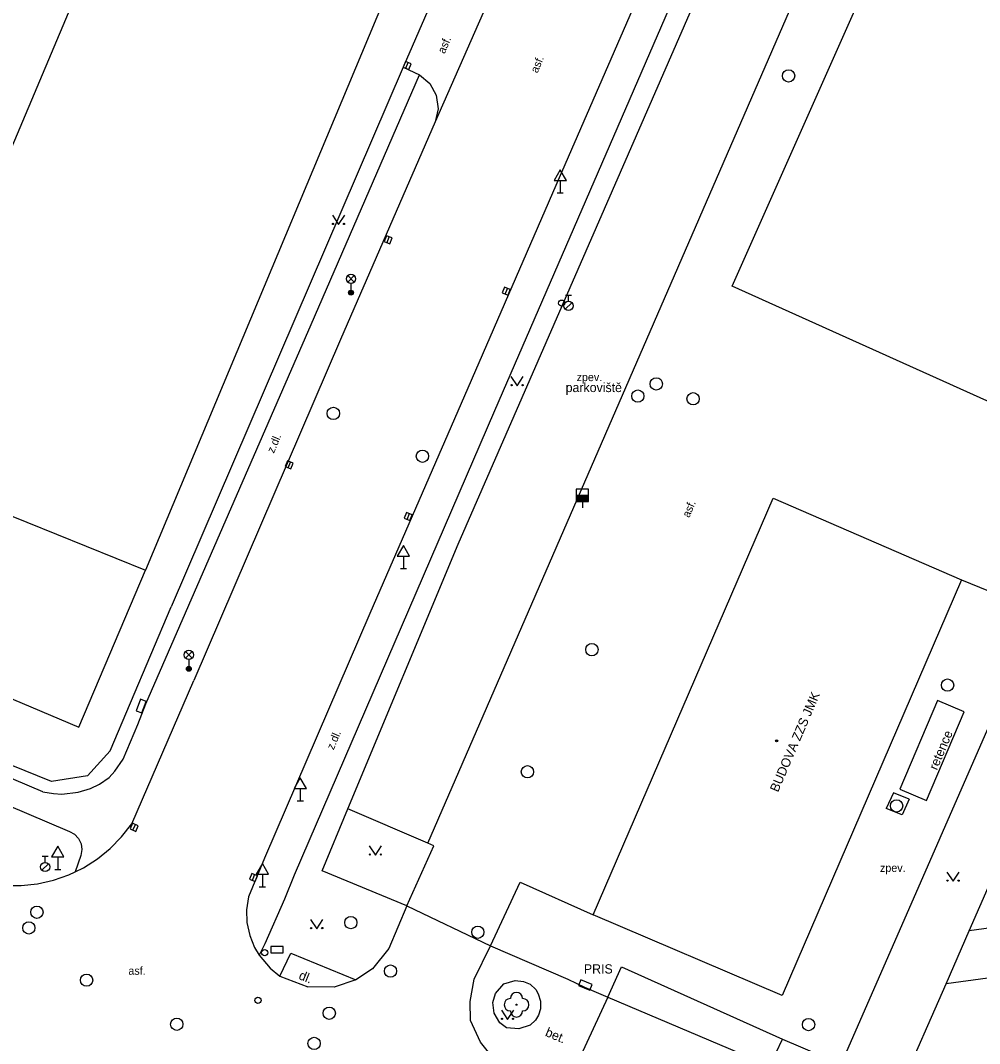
# Model space of a CAD drawing. Extents: x -596024 to -594475, y -1163820 to -1161957.
# Drawn here: x -594753.9 to -594676, y -1162375 to -1162292 of the extents above; entities that cross this region are included whole.
import ezdxf

# ---------------------------------------------------------------- set-up
doc = ezdxf.new("R2010")
doc.units = 0
for name, color, linetype in [('Level 10', 7, 'Continuous'), ('Level 11', 7, 'Continuous'), ('Level 22', 7, 'Continuous'), ('Level 24', 7, 'Continuous'), ('Level 27', 7, 'Continuous'), ('Level 28', 7, 'Continuous'), ('Level 33', 7, 'Continuous'), ('Level 34', 7, 'Continuous'), ('Level 36', 7, 'Continuous'), ('Level 39', 7, 'Continuous'), ('Level 40', 7, 'Continuous'), ('Level 41', 7, 'Continuous'), ('Level 42', 7, 'Continuous'), ('Level 43', 7, 'Continuous'), ('Level 5', 7, 'Continuous'), ('Level 7', 7, 'Continuous'), ('Level 8', 7, 'Continuous')]:
    doc.layers.add(name, color=color, linetype=linetype)

msp = doc.modelspace()

# ---------------------------------------------------------------- linework, layer by layer
at = {"layer": 'Level 10'}
for points in [[(-594702.69, -1162287.55), (-594710.41, -1162305.36), (-594717.82, -1162322.43), (-594725.53, -1162340.1), (-594734.07, -1162359.95), (-594735.38, -1162363.09)], [(-594714.72, -1162287.68), (-594720.21, -1162300.18)], [(-594720.21, -1162300.18), (-594727.89, -1162317.86), (-594739.81, -1162345.52)], [(-594744.85, -1162357.18), (-594739.81, -1162345.52)], [(-594749.43, -1162361.06), (-594748.76, -1162360.73), (-594747.63, -1162360.01), (-594746.6, -1162359.18), (-594745.67, -1162358.23), (-594744.85, -1162357.18)], [(-594759.02, -1162361.25), (-594757.77, -1162361.71), (-594756.48, -1162362.02), (-594755.16, -1162362.18), (-594753.83, -1162362.18), (-594752.51, -1162362.04), (-594751.21, -1162361.75), (-594749.95, -1162361.31), (-594749.43, -1162361.06)], [(-594735.38, -1162363.09), (-594735.53, -1162364.14), (-594735.49, -1162365.19), (-594735.27, -1162366.23), (-594734.87, -1162367.21), (-594734.51, -1162367.83)], [(-594722.52, -1162363.83), (-594723.98, -1162367.29), (-594725.3, -1162368.93), (-594726.65, -1162369.84)], [(-594722.52, -1162363.83), (-594715.71, -1162367.06)], [(-594715.21, -1162376.53), (-594716.54, -1162374.89), (-594717.34, -1162373.13), (-594717.37, -1162371.6), (-594717.05, -1162369.79), (-594715.71, -1162367.06)], [(-594734.51, -1162367.83), (-594733.61, -1162368.89)], [(-594733.61, -1162368.89), (-594732.83, -1162369.53)], [(-594732.83, -1162369.53), (-594730.54, -1162370.41)], [(-594726.65, -1162369.84), (-594728.42, -1162370.43), (-594730.54, -1162370.41)]]:
    msp.add_lwpolyline(points, dxfattribs=at)
at = {"layer": 'Level 11'}
for points in [[(-594682.2, -1162247.11), (-594684.47, -1162252.23), (-594693.08, -1162272.1), (-594700.25, -1162288.69), (-594715.41, -1162323.63)], [(-594736.89, -1162272.33), (-594719.88, -1162279.55), (-594743.74, -1162336.57)], [(-594718.34, -1162334.47), (-594696.72, -1162284.88), (-594694.07, -1162278.81), (-594689.66, -1162280.67)], [(-594719.88, -1162279.55), (-594716.51, -1162281.14), (-594719.82, -1162288.82), (-594722.8, -1162295.75), (-594741.65, -1162339.55)], [(-594687.26, -1162376.68), (-594671.17, -1162339.92), (-594665.63, -1162327.25), (-594696.11, -1162313.53), (-594685.6, -1162289.88), (-594682.8, -1162283.58)], [(-594720.8, -1162358.74), (-594690.02, -1162287.83), (-594696.72, -1162284.88)], [(-594722.8, -1162295.75), (-594721.48, -1162296.37)], [(-594744.34, -1162349.11), (-594743.71, -1162347.44), (-594730.27, -1162316.63), (-594721.48, -1162296.37)], [(-594721.48, -1162296.37), (-594720.65, -1162297.08), (-594720.12, -1162298.03), (-594719.97, -1162299.12), (-594720.21, -1162300.18)], [(-594715.41, -1162323.63), (-594731.66, -1162361.34)], [(-594765.42, -1162327.81), (-594743.74, -1162336.57)], [(-594752.07, -1162354.57), (-594762.07, -1162350.31), (-594773.85, -1162345.29), (-594804.52, -1162332.02)], [(-594806.31, -1162333.82), (-594774.887, -1162347.169), (-594749.91, -1162357.78)], [(-594677.49, -1162337.37), (-594671.17, -1162339.92)], [(-594745.53, -1162351.93), (-594744.34, -1162349.11)], [(-594752.07, -1162354.57), (-594751.207, -1162354.712), (-594750.51, -1162354.75), (-594749.207, -1162354.585), (-594748.191, -1162354.299), (-594747.461, -1162353.95), (-594746.676, -1162353.412), (-594746.223, -1162352.886), (-594745.53, -1162351.93)], [(-594722.52, -1162363.83), (-594720.33, -1162358.95), (-594720.8, -1162358.74), (-594727.3, -1162355.94)], [(-594749.91, -1162357.78), (-594749.5, -1162358.01), (-594749.17, -1162358.36), (-594748.96, -1162358.79), (-594748.9, -1162359.26), (-594748.97, -1162359.73)], [(-594748.97, -1162359.73), (-594749.43, -1162361.06)], [(-594731.66, -1162361.34), (-594732.45, -1162363.28), (-594734.03, -1162366.9), (-594734.51, -1162367.83)], [(-594715.71, -1162367.06), (-594713.31, -1162361.91), (-594707.38, -1162364.56)], [(-594658.45, -1162363.35), (-594676.86, -1162365.85)], [(-594732.83, -1162369.53), (-594731.92, -1162367.67), (-594726.65, -1162369.84)], [(-594658.03, -1162367.34), (-594678.74, -1162370.15)], [(-594706.2, -1162371.24), (-594705.09, -1162368.77), (-594692.01, -1162374.65)], [(-594715.42, -1162372.53), (-594715.53, -1162371.66), (-594715.32, -1162370.94), (-594714.64, -1162370.16), (-594713.73, -1162369.89), (-594713.03, -1162369.96), (-594712.5, -1162370.19), (-594712.04, -1162370.61)], [(-594712.04, -1162370.61), (-594711.84, -1162370.96)], [(-594711.84, -1162370.96), (-594711.65, -1162371.56)], [(-594706.2, -1162371.24), (-594709.76, -1162378.95)], [(-594711.65, -1162371.56), (-594711.66, -1162372.2), (-594711.83, -1162372.69), (-594712.08, -1162373.12), (-594712.51, -1162373.5), (-594713.41, -1162373.8), (-594714.42, -1162373.72), (-594714.96, -1162373.32), (-594715.42, -1162372.53)]]:
    msp.add_lwpolyline(points, dxfattribs=at)
at = {"layer": 'Level 22'}
msp.add_circle((-594713.61, -1162371.85), 0.05, dxfattribs=at)
for centre, start, end in [((-594714.11, -1162371.85), 90, 270), ((-594713.61, -1162371.35), 0, 180), ((-594713.11, -1162371.85), 270, 90), ((-594713.61, -1162372.35), 180, 0)]:
    msp.add_arc(centre, 0.5, start, end, dxfattribs=at)
at = {"layer": 'Level 24'}
for points in [[(-594744.033, -1162348.167), (-594743.662, -1162347.238), (-594744.127, -1162347.053), (-594744.498, -1162347.982)], [(-594733.55, -1162367.64), (-594732.55, -1162367.64), (-594732.55, -1162367.14), (-594733.55, -1162367.14)], [(-594708.578, -1162370.29), (-594707.653, -1162370.672), (-594707.462, -1162370.21), (-594708.387, -1162369.828)]]:
    msp.add_lwpolyline(points, close=True, dxfattribs=at)
at = {"layer": 'Level 27'}
for p, q in [((-594722.585, -1162295.831), (-594722.395, -1162295.369)), ((-594724.122, -1162309.982), (-594723.938, -1162309.518)), ((-594714.532, -1162314.162), (-594714.348, -1162313.698)), ((-594732.152, -1162328.262), (-594731.968, -1162327.798)), ((-594722.492, -1162332.452), (-594722.308, -1162331.988)), ((-594744.751, -1162357.679), (-594744.549, -1162357.221)), ((-594735.052, -1162361.762), (-594734.868, -1162361.298))]:
    msp.add_line(p, q, dxfattribs=at)
for points in [[(-594722.354, -1162295.926), (-594722.164, -1162295.464), (-594722.626, -1162295.274), (-594722.816, -1162295.736)], [(-594723.89, -1162310.075), (-594723.705, -1162309.61), (-594724.17, -1162309.425), (-594724.355, -1162309.89)], [(-594714.3, -1162314.255), (-594714.115, -1162313.79), (-594714.58, -1162313.605), (-594714.765, -1162314.07)], [(-594731.92, -1162328.355), (-594731.735, -1162327.89), (-594732.2, -1162327.705), (-594732.385, -1162328.17)], [(-594722.26, -1162332.544), (-594722.075, -1162332.08), (-594722.54, -1162331.895), (-594722.725, -1162332.36)], [(-594744.523, -1162357.78), (-594744.32, -1162357.323), (-594744.777, -1162357.12), (-594744.98, -1162357.577)], [(-594734.82, -1162361.855), (-594734.635, -1162361.39), (-594735.1, -1162361.205), (-594735.285, -1162361.67)]]:
    msp.add_lwpolyline(points, close=True, dxfattribs=at)
for centre in [(-594691.52, -1162296.45), (-594702.26, -1162321.46), (-594703.76, -1162322.44), (-594699.27, -1162322.66), (-594728.48, -1162323.85), (-594721.25, -1162327.33), (-594707.49, -1162343.03), (-594678.62, -1162345.91), (-594712.72, -1162352.94), (-594682.75, -1162355.71), (-594752.54, -1162364.34), (-594727.06, -1162365.19), (-594753.2, -1162365.62), (-594716.75, -1162365.97), (-594723.84, -1162369.12), (-594748.51, -1162369.86), (-594728.81, -1162372.54), (-594741.19, -1162373.44), (-594689.9, -1162373.47), (-594730.04, -1162374.99)]:
    msp.add_circle(centre, 0.5, dxfattribs=at)
at = {"layer": 'Level 28'}
for p, q in [((-594709.648, -1162315.392), (-594709.118, -1162314.862)), ((-594709.64, -1162314.245), (-594709.14, -1162314.245)), ((-594709.39, -1162314.745), (-594709.39, -1162314.245)), ((-594708.76, -1162330.49), (-594707.76, -1162330.49)), ((-594708.76, -1162330.54), (-594707.76, -1162330.54)), ((-594708.76, -1162330.59), (-594707.76, -1162330.59)), ((-594708.76, -1162330.64), (-594707.76, -1162330.64)), ((-594708.76, -1162330.69), (-594707.76, -1162330.69)), ((-594708.76, -1162330.74), (-594707.76, -1162330.74)), ((-594708.76, -1162330.79), (-594707.76, -1162330.79)), ((-594708.76, -1162330.84), (-594707.76, -1162330.84)), ((-594708.76, -1162330.89), (-594707.76, -1162330.89)), ((-594708.76, -1162330.94), (-594707.76, -1162330.94)), ((-594708.26, -1162330.99), (-594708.26, -1162331.52)), ((-594752.13, -1162359.795), (-594751.63, -1162359.795)), ((-594751.88, -1162360.295), (-594751.88, -1162359.795)), ((-594752.138, -1162360.942), (-594751.608, -1162360.412))]:
    msp.add_line(p, q, dxfattribs=at)
msp.add_lwpolyline([(-594708.76, -1162330.99), (-594707.76, -1162330.99), (-594707.76, -1162329.99), (-594708.76, -1162329.99)], close=True, dxfattribs=at)
for centre, radius in [((-594709.94, -1162314.9), 0.25), ((-594709.39, -1162315.12), 0.375), ((-594751.88, -1162360.67), 0.375), ((-594734.05, -1162367.63), 0.25), ((-594734.6, -1162371.5), 0.25)]:
    msp.add_circle(centre, radius, dxfattribs=at)
at = {"layer": 'Level 33'}
for p, q in [((-594727.315, -1162313.19), (-594726.785, -1162312.66)), ((-594727.315, -1162312.66), (-594726.785, -1162313.19)), ((-594727.05, -1162313.3), (-594727.05, -1162314.05)), ((-594740.475, -1162343.72), (-594739.945, -1162343.19)), ((-594740.475, -1162343.19), (-594739.945, -1162343.72)), ((-594740.21, -1162343.83), (-594740.21, -1162344.58))]:
    msp.add_line(p, q, dxfattribs=at)
for centre, radius in [((-594727.05, -1162312.925), 0.375), ((-594727.05, -1162314.05), 0.2), ((-594727.05, -1162314.05), 0.145), ((-594727.05, -1162314.05), 0.0876), ((-594740.21, -1162343.455), 0.375), ((-594740.21, -1162344.58), 0.2), ((-594740.21, -1162344.58), 0.145), ((-594740.21, -1162344.58), 0.0876)]:
    msp.add_circle(centre, radius, dxfattribs=at)
at = {"layer": 'Level 34'}
for p, q in [((-594710.06, -1162304.932), (-594710.06, -1162305.95)), ((-594710.31, -1162305.95), (-594709.81, -1162305.95)), ((-594722.79, -1162335.432), (-594722.79, -1162336.45)), ((-594723.04, -1162336.45), (-594722.54, -1162336.45)), ((-594731.16, -1162354.292), (-594731.16, -1162355.31)), ((-594731.41, -1162355.31), (-594730.91, -1162355.31)), ((-594750.85, -1162359.852), (-594750.85, -1162360.87)), ((-594751.1, -1162360.87), (-594750.6, -1162360.87)), ((-594734.24, -1162361.262), (-594734.24, -1162362.28)), ((-594734.49, -1162362.28), (-594733.99, -1162362.28))]:
    msp.add_line(p, q, dxfattribs=at)
for points in [[(-594710.56, -1162304.932), (-594709.56, -1162304.932), (-594710.06, -1162304.066)], [(-594723.29, -1162335.432), (-594722.29, -1162335.432), (-594722.79, -1162334.566)], [(-594731.66, -1162354.292), (-594730.66, -1162354.292), (-594731.16, -1162353.426)], [(-594751.35, -1162359.852), (-594750.35, -1162359.852), (-594750.85, -1162358.986)], [(-594734.74, -1162361.262), (-594733.74, -1162361.262), (-594734.24, -1162360.396)]]:
    msp.add_lwpolyline(points, close=True, dxfattribs=at)
at = {"layer": 'Level 36'}
for points in [[(-594728.56, -1162307.77), (-594728.06, -1162308.52), (-594727.56, -1162307.77)], [(-594714.06, -1162320.86), (-594713.56, -1162321.61), (-594713.06, -1162320.86)], [(-594725.57, -1162358.96), (-594725.07, -1162359.71), (-594724.57, -1162358.96)], [(-594678.67, -1162361.08), (-594678.17, -1162361.83), (-594677.67, -1162361.08)], [(-594730.33, -1162364.93), (-594729.83, -1162365.68), (-594729.33, -1162364.93)], [(-594714.84, -1162372.3), (-594714.34, -1162373.05), (-594713.84, -1162372.3)]]:
    msp.add_lwpolyline(points, dxfattribs=at)
for centre in [(-594728.51, -1162308.47), (-594727.611, -1162308.47), (-594714.01, -1162321.56), (-594713.111, -1162321.56), (-594725.52, -1162359.66), (-594724.621, -1162359.66), (-594678.62, -1162361.78), (-594677.721, -1162361.78), (-594730.28, -1162365.63), (-594729.381, -1162365.63), (-594714.79, -1162373), (-594713.891, -1162373)]:
    msp.add_circle(centre, 0.05, dxfattribs=at)
at = {"layer": 'Level 39'}
for radius in [0.09, 0.0398]:
    msp.add_circle((-594692.49, -1162350.43), radius, dxfattribs=at)
at = {"layer": 'Level 43'}
for points in [[(-594679.44, -1162347.17), (-594682.49, -1162354.35)], [(-594677.27, -1162348.09), (-594679.44, -1162347.17)], [(-594680.32, -1162355.27), (-594677.27, -1162348.09)], [(-594683.01, -1162354.65), (-594683.59, -1162355.93)], [(-594681.73, -1162355.16), (-594683.01, -1162354.65)], [(-594682.49, -1162354.35), (-594680.32, -1162355.27)], [(-594681.73, -1162355.16), (-594682.31, -1162356.44)], [(-594682.31, -1162356.44), (-594683.59, -1162355.93)]]:
    msp.add_lwpolyline(points, dxfattribs=at)
at = {"layer": 'Level 5'}
for points in [[(-594750.01, -1162291.36), (-594760.22, -1162315.51)], [(-594707.38, -1162364.56), (-594692.77, -1162330.72), (-594677.49, -1162337.37), (-594692.03, -1162371.11), (-594707.38, -1162364.56)], [(-594749.13, -1162349.32), (-594743.74, -1162336.57)], [(-594755.34, -1162346.7), (-594749.13, -1162349.32)]]:
    msp.add_lwpolyline(points, dxfattribs=at)
at = {"layer": 'Level 7'}
for points in [[(-594678.74, -1162370.15), (-594676.86, -1162365.85), (-594665.04, -1162338.87), (-594663.21, -1162334.69), (-594662.82, -1162333.79)], [(-594722.52, -1162363.83), (-594729.4, -1162360.99), (-594727.3, -1162355.94), (-594718.34, -1162334.47)], [(-594746.61, -1162351.23), (-594741.65, -1162339.55)], [(-594746.61, -1162351.23), (-594748.45, -1162353.26)], [(-594751.37, -1162353.74), (-594756.8, -1162351.55)], [(-594748.45, -1162353.26), (-594751.37, -1162353.74)], [(-594715.71, -1162367.06), (-594709.43, -1162369.79)], [(-594708.09, -1162370.42), (-594706.2, -1162371.24)], [(-594706.2, -1162371.24), (-594693.04, -1162376.81), (-594692.01, -1162374.65), (-594687.26, -1162376.68), (-594682.49, -1162378.72), (-594678.74, -1162370.15)]]:
    msp.add_lwpolyline(points, dxfattribs=at)
at = {"layer": 'Level 8'}
msp.add_lwpolyline([(-594709.43, -1162369.79), (-594708.09, -1162370.42)], dxfattribs=at)

# ---------------------------------------------------------------- texts
at = {"layer": 'Level 40'}
for s, height, rotation, p in [('asf.', 0.65, 66.68, (-594719.45, -1162294.7)), ('asf.', 0.65, 66.96, (-594711.91, -1162296.27)), ('z.dl.', 0.65, 66.84, (-594733.31, -1162327.13)), ('asf.', 0.65, 66.78, (-594699.59, -1162332.36)), ('z.dl.', 0.65, 66.84, (-594728.46, -1162351.21)), ('dl.', 0.75, 338, (-594731.35, -1162369.75)), ('bet.', 0.75, 337, (-594711.34, -1162374.36))]:
    msp.add_text(s, height=height, rotation=rotation, dxfattribs=at).set_placement(p)
for s, p in [('zpev.', (-594708.73, -1162321.23)), ('zpev.', (-594684.1, -1162361.07)), ('asf.', (-594745.12, -1162369.42))]:
    msp.add_text(s, height=0.65, dxfattribs=at).set_placement(p)
at = {"layer": 'Level 41'}
msp.add_text('BUDOVA ZZS JMK', height=0.75, rotation=66.83, dxfattribs=at).set_placement((-594692.38, -1162354.65))
msp.add_text('PRIS', height=0.75, dxfattribs=at).set_placement((-594708.14, -1162369.32))
at = {"layer": 'Level 42'}
msp.add_text('parkoviště', height=0.75, dxfattribs=at).set_placement((-594709.62, -1162322.12))
msp.add_text('retence', height=0.75, rotation=67, dxfattribs=at).set_placement((-594679.48, -1162352.86))

doc.saveas('drawing.dxf')
